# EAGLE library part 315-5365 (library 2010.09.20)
The 315-5365 Paging Chip The 315-5365 can handle 32 &times; 16KB ROM pages, giving a total of 512KB addressable space. It supports paging in frames 0 (cartridge address 0x400-0x3FFF), 1 (0x4000-0x7FFF), and 2 (0x8000-0xBFFF). It is unknown whether this chip supports SRAM. ROM TYPElow (GND)HIGH (VCC) CE00x000000&mdash;0x7FFFF0x00000&mdash;0x1FFFF CE10x400000&mdash;0x7FFFF0x40000&mdash;0x7FFFF CE20x000000&mdash;0x3FFFF0x20000&mdash;0x3FFFF Information in this document is compiled from postings by Mike G. and Charles Mac Donald on the S8-Dev Forum, and from personal investigations by Zoop and Eric Quinn. Drawn by Darren Lue Choy 2010.09.20
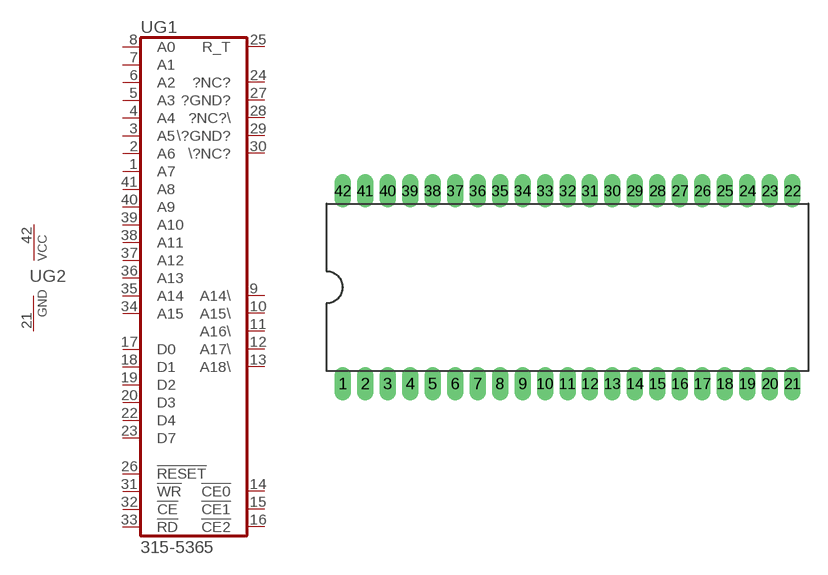
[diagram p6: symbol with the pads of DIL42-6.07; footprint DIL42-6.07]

Designator prefix -; gates G1=315-5365 G2=PWRN

## 315-5365  [DIL42-6.07]
1  G1:A7  in
2  G1:A6  in
3  G1:A5  in
4  G1:A4  in
5  G1:A3  in
6  G1:A2  in
7  G1:A1  in
8  G1:A0  in
9  G1:A14\  out
10  G1:A15\  out
11  G1:A16\  out
12  G1:A17\  out
13  G1:A18\  out
14  G1:!CE0  out
15  G1:!CE1  out
16  G1:!CE2  out
17  G1:D0  in
18  G1:D1  in
19  G1:D2  in
20  G1:D3  in
21  G2:GND  pwr
22  G1:D4  in
23  G1:D7  in
24  G1:?NC?
25  G1:R_T  in
26  G1:!RESET  in
27  G1:?GND?  in
28  G1:?NC?\
29  G1:\?GND?  in
30  G1:\?NC?
31  G1:!WR  in
32  G1:!CE  in
33  G1:!RD  in
34  G1:A15  in
35  G1:A14  in
36  G1:A13  in
37  G1:A12  in
38  G1:A11  in
39  G1:A10  in
40  G1:A9  in
41  G1:A8  in
42  G2:VCC  pwr

## Footprint DIL42-6.07 (pad centres in mm)
Dual In Line Package 0.6 inch 0.07 pitch Drawn by D Lue Choy &micro; 2010.09.20
drill 0.813 long: 1 -17.78,-7.62; 2 -16.002,-7.62; 3 -14.224,-7.62; 4 -12.446,-7.62; 5 -10.668,-7.62; 6 -8.89,-7.62; 7 -7.112,-7.62; 8 -5.334,-7.62; 9 -3.556,-7.62; 10 -1.778,-7.62; 11 0,-7.62; 12 1.778,-7.62; 13 3.556,-7.62; 14 5.334,-7.62; 15 7.112,-7.62; 16 8.89,-7.62; 17 10.668,-7.62; 18 12.446,-7.62; 19 14.224,-7.62; 20 16.002,-7.62; 21 17.78,-7.62; 22 17.78,7.62; 23 16.002,7.62; 24 14.224,7.62; 25 12.446,7.62; 26 10.668,7.62; 27 8.89,7.62; 28 7.112,7.62; 29 5.334,7.62; 30 3.556,7.62; 31 1.778,7.62; 32 0,7.62; 33 -1.778,7.62; 34 -3.556,7.62; 35 -5.334,7.62; 36 -7.112,7.62; 37 -8.89,7.62; 38 -10.668,7.62; 39 -12.446,7.62; 40 -14.224,7.62; 41 -16.002,7.62; 42 -17.78,7.62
